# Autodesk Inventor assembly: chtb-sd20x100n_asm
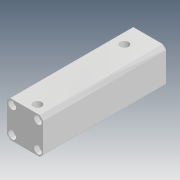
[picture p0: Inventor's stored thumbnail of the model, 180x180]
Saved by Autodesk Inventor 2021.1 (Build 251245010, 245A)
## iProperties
Company: Microsoft
Created: 2018-04
Part Number: chtb-sd20x100n_asm
Description: STEP AP214
Document SubType Name: Assembly
Designer: user
Title: chtb-sd20x100n_asm.STEP
Author: Windows
Revision Number: ÈÎºÎ
Sending System: SolidWorks 2015
Preprocessor: SwSTEP 2.0
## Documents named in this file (4)
- D:\Vault_2016\Projekty\Clamptek\Hydraulic\CHTB\CHTB-20\Inventor\CHTB-SD20x100N\chtb-sd20x100n_asm.iam
- D:\Vault_2016\Projekty\Clamptek\Hydraulic\CHTB\CHTB-20\Inventor\CHTB-SD20x100N\CHTB-SD20X100NBT.ipt
- D:\Vault_2016\Projekty\Clamptek\Hydraulic\CHTB\CHTB-20\Inventor\CHTB-SD20x100N\CHTB-SD20X100NHSG.ipt
- D:\Vault_2016\Projekty\Clamptek\Hydraulic\CHTB\CHTB-20\Inventor\CHTB-SD20x100N\QG.ipt
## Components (3 placed, 3 different names)
1. CHTB-SD20X100NBT_1
2. CHTB-SD20X100NHSG_2
3. QG_3
